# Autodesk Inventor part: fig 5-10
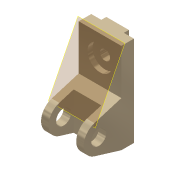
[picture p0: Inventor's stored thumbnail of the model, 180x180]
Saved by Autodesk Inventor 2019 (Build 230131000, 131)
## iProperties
Shininess: 65.0
Angle Display Precision: 2
Document Length Units: 11269
Document Angle Units: 11279
Document Time Units: 11290
Document Mass Units: 11283
Document Length Units Precision: 3
Document Angle Units Precision: 2
Compacted: False
Created: 2001-11
Part Number: fig 5-10
Document SubType Name: Modeling
Designer: Renu Muthoo
Density: 1 g/cm^3
Material: Generic
Appearance: Metal-Titanium (Polished)
Density: 0.0
Volumn: 0.0
Area: 0.0
PropertySet Name: Model Information
Control State: 0
Master: False
Checked Out: False
Author: Renu Muthoo
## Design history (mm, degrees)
node "Sketch1"
sketch "Sketch2"
  geometry: L1 (33.257, 104.664)-(33.257, -75.336); L2 (33.257, -75.336)-(8.257, -75.336); L3 (8.257, -75.336)-(-45.451, -59.045); L4 (-45.451, -1.628)-(8.257, 14.664); L5 (8.257, 14.664)-(8.257, 104.664); L6 (8.257, 104.664)-(33.257, 104.664); C1 r 15 at (-36.743, -30.336); A1 r 30 centre (-36.743, -30.336) between (-45.451, -1.628) and (-45.451, -59.045)
  constraints: 12 end point, 2 centre point, 2 equal length, 2 parallel, 2 point on circle, 2 tangent, 1 coincident, 1 perpendicular, 1 vertical
  dimensions: "d0" = 180 distance of L1.start L1.end; "d1" = 30 radius of A1; "d2" = 25 distance of L5.end L1.start; "d3" = 45 distance from line of L2 A1.centre; "d4" = 70 distance from line of L1 A1.centre; "d5" = 30 diameter of C1
extrude "Extrusion1" new body sketch "Sketch2" distance "d6" = 85; taper "d7" = 0 deg
workplane "Work Plane1"
sketch "Sketch3"
  geometry: L1 (15, 62.364)-(70, 62.364); L2 (70, 62.364)-(70, -52.386); L3 (70, -52.386)-(15, -52.386); L4 (15, -52.386)-(15, 62.364); L5 (0, -45)-(0, -28.708) reference
  constraints: 8 end point, 2 parallel, 1 horizontal, 1 perpendicular
  dimensions: "d8" = 55 distance of L1.start L1.end; "d9" = 15 distance between parallel lines of L5 L4
extrude "Extrusion2" cut sketch "Sketch3" distance "d10" = 50; taper "d11" = 0 deg
sketch "Sketch4"
  geometry: L1 (0, 25)-(85, 25) reference; L2 (0, 0)-(0, 25) reference; L3 (20, 25)-(65, 25); L4 (65, 25)-(65, 35); L5 (65, 35)-(20, 35); L6 (20, 35)-(20, 25)
  constraints: 8 end point, 2 parallel, 1 horizontal, 1 perpendicular, 1 point on line
  dimensions: "d12" = 45 distance of L4.end L5.end; "d13" = 10 distance of L3.end L4.end; "d14" = 20 distance between parallel lines of L2 L6
extrude "Extrusion3" join sketch "Sketch4" stored distance "d15" = 50; taper "d16" = 0 deg
sketch "Sketch5"
  geometry: L1 (85, 0)-(85, 90) reference; L2 (0, 90)-(85, 90) reference; 1 further point
  dimensions: "d17" = 42 distance from line of L2 point (42.5, 48); "d18" = 42.5 distance from line of L1 point (42.5, 48)
hole "Hole1" sketch "Sketch5" at (42.5, 48) diameter "d19" = 20; stored, may be unused: countersink angle "d23" = 82 deg, drill point angle "d25" = 118 deg; dims "d20" = 6, "d21" = 50, "d22" = 10, "d24" = 8
workplane "Work Plane4"
body "Solid1"
